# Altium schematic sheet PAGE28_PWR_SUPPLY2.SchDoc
size 431 x 304 mm; SheetNumber: 28; SheetTotal: 28
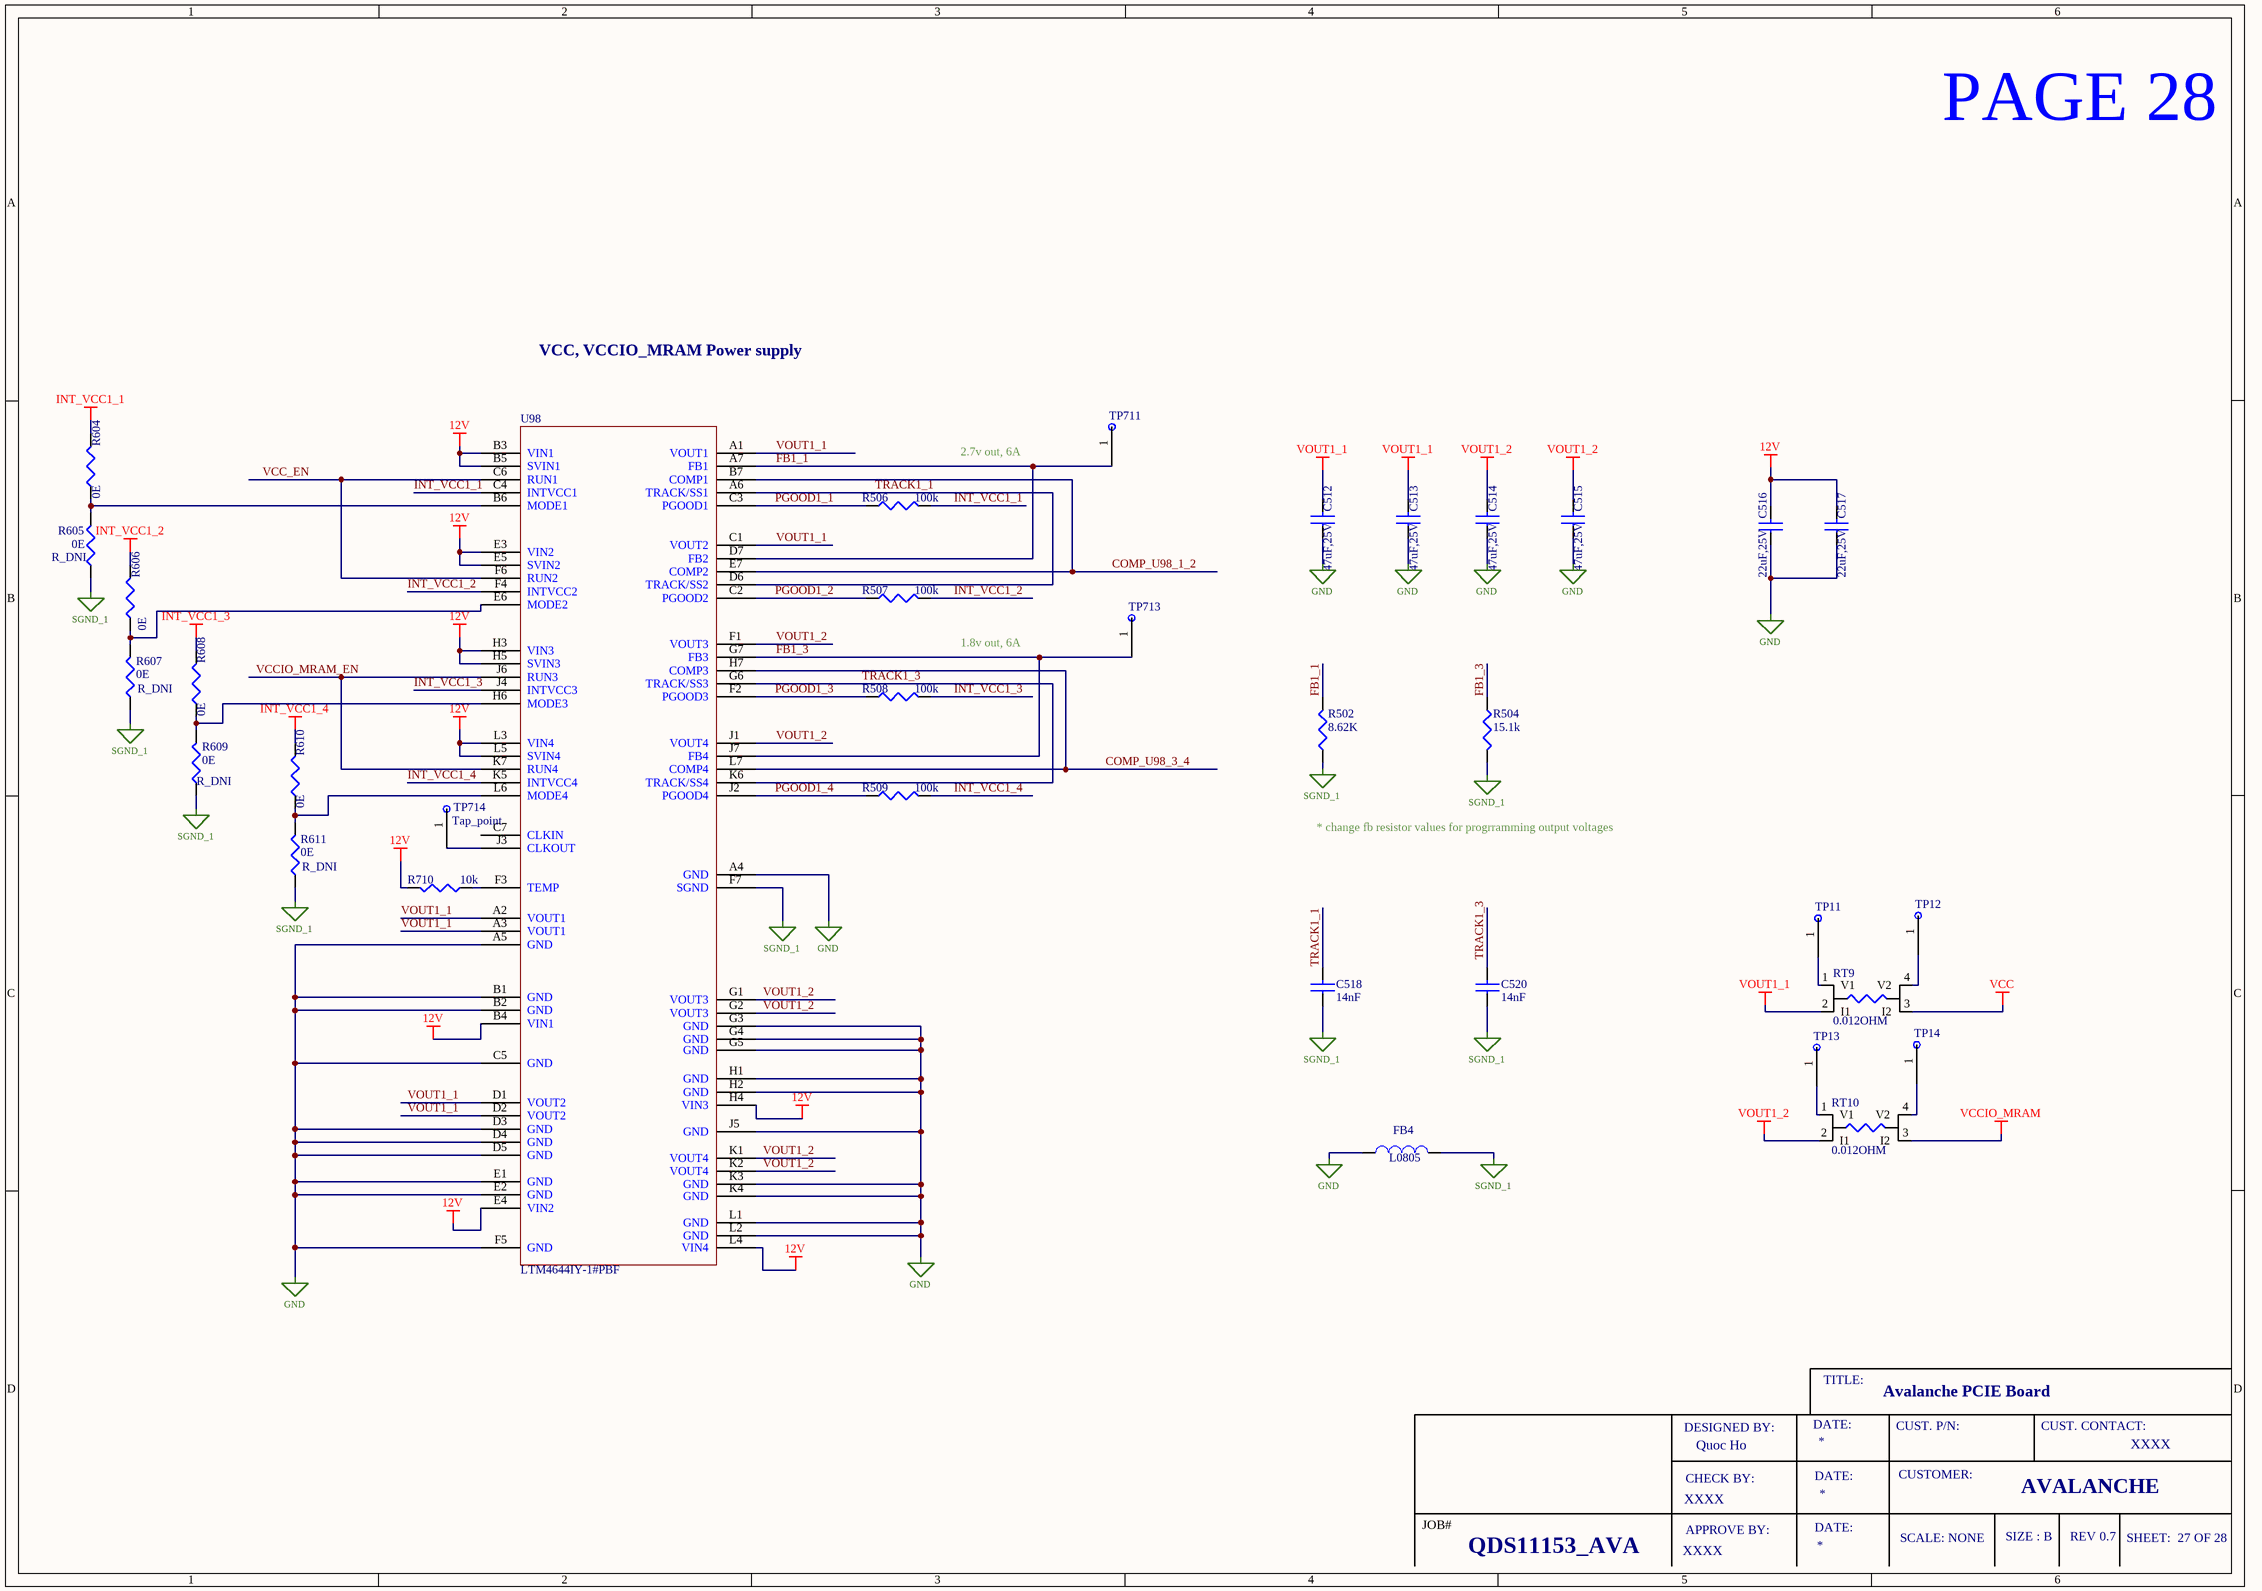
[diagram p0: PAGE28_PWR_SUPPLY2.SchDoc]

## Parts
C512  47uF,25V  [CN_1210]
C513  47uF,25V  [CN_1210]
C514  47uF,25V  [CN_1210]
C515  47uF,25V  [CN_1210]
C516  22uF,25V  [CN_1210]
C517  22uF,25V  [CN_1210]
C518  14nF  [CN_0402]
C520  14nF  [CN_0402]
FB4  L0805  [L0805]
R502  8.62K  [RN_0402]
R504  15.1k  [RN_0402]
R506  100k  [RN_0402]
R507  100k  [RN_0402]
R508  100k  [RN_0402]
R509  100k  [RN_0402]
R604  0E  [RN_0402]
R605  0E  [RN_0402]
R606  0E  [RN_0402]
R607  0E  [RN_0402]
R608  0E  [RN_0402]
R609  0E  [RN_0402]
R610  0E  [RN_0402]
R611  0E  [RN_0402]
R710  10k  [RN_0402]
RT9  0.012OHM  [LVK12]
RT10  0.012OHM  [LVK12]
TP11  Tap_point  [MINI_TESTPOINT_SMD]  (value not drawn)
TP12  Tap_point  [MINI_TESTPOINT_SMD]  (value not drawn)
TP13  Tap_point  [MINI_TESTPOINT_SMD]  (value not drawn)
TP14  Tap_point  [MINI_TESTPOINT]  (value not drawn)
TP711  Tap_point  [MINI_TESTPOINT_SMD]  (value not drawn)
TP713  Tap_point  [MINI_TESTPOINT]  (value not drawn)
TP714  Tap_point  [MINI_TESTPOINT]
U98  LTM4644IY-1#PBF  [BGA77_15X9X1P5_ANALOG]

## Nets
12V: C516.2 C517.2 R710.2 U98.B3(VIN1) U98.B4(VIN1) U98.B5(SVIN1) U98.E3(VIN2) U98.E4(VIN2) U98.E5(SVIN2) U98.H3(VIN3) U98.H4(VIN3) U98.H5(SVIN3) U98.L3(VIN4) U98.L4(VIN4) U98.L5(SVIN4)
GND: C512.1 C513.1 C514.1 C515.1 C516.1 C517.1 FB4.1 U98.A4(GND) U98.A5(GND) U98.B1(GND) U98.B2(GND) U98.C5(GND) U98.D3(GND) U98.D4(GND) U98.D5(GND) U98.E1(GND) U98.E2(GND) U98.F5(GND) U98.G3(GND) U98.G4(GND) U98.G5(GND) U98.H1(GND) U98.H2(GND) U98.J5(GND) U98.K3(GND) U98.K4(GND) U98.L1(GND) U98.L2(GND)
INT_VCC1_1: R506.2 R604.2 U98.C4(INTVCC1)
INT_VCC1_2: R507.2 R606.2 U98.F4(INTVCC2)
INT_VCC1_3: R508.2 R608.2 U98.J4(INTVCC3)
INT_VCC1_4: R509.2 R610.2 U98.K5(INTVCC4)
SGND_1: C518.1 C520.1 FB4.2 R502.1 R504.2 R605.1 R607.1 R609.1 R611.1 U98.F7(SGND)
VCC: RT9.3(I2)
VCCIO_MRAM: RT10.3(I2)
VOUT1_1: C512.2 C513.2 RT9.2(I1) U98.A1(VOUT1) U98.A2(VOUT1) U98.A3(VOUT1) U98.C1(VOUT2) U98.D1(VOUT2) U98.D2(VOUT2)
VOUT1_2: C514.2 C515.2 RT10.2(I1) U98.F1(VOUT3) U98.G1(VOUT3) U98.G2(VOUT3) U98.J1(VOUT4) U98.K1(VOUT4) U98.K2(VOUT4)
COMP_U98_1_2: U98.B7(COMP1) U98.E7(COMP2)
COMP_U98_3_4: U98.H7(COMP3) U98.L7(COMP4)
FB1_1: R502.2 TP711.1 U98.A7(FB1) U98.D7(FB2)
FB1_3: R504.1 TP713.1 U98.G7(FB3) U98.J7(FB4)
PGOOD1_1: R506.1 U98.C3(PGOOD1)
PGOOD1_2: R507.1 U98.C2(PGOOD2)
PGOOD1_3: R508.1 U98.F2(PGOOD3)
PGOOD1_4: R509.1 U98.J2(PGOOD4)
TRACK1_1: C518.2 U98.A6(TRACK/SS1) U98.D6(TRACK/SS2)
TRACK1_3: C520.2 U98.G6(TRACK/SS3) U98.K6(TRACK/SS4)
VCC_EN: U98.C6(RUN1) U98.F6(RUN2)
VCCIO_MRAM_EN: U98.J6(RUN3) U98.K7(RUN4)
NetR604_1: R604.1 R605.2 U98.B6(MODE1)
NetR606_1: R606.1 R607.2 U98.E6(MODE2)
NetR608_1: R608.1 R609.2 U98.H6(MODE3)
NetR610_1: R610.1 R611.2 U98.L6(MODE4)
NetR710_1: R710.1 U98.F3(TEMP)
NetRT9_1: RT9.1(V1) TP11.1
NetRT9_4: RT9.4(V2) TP12.1
NetRT10_1: RT10.1(V1) TP13.1
NetRT10_4: RT10.4(V2) TP14.1
NetTP714_1: TP714.1 U98.J3(CLKOUT)

Not connected (* = marked no-connect by the designer): U98 C7(CLKIN)

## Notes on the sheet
- PAGE 28
- VCC, VCCIO_MRAM Power supply
- 2.7v out, 6A
- 1.8v out, 6A
- * change fb resistor values for progrramming output voltages
- TITLE:
- Avalanche PCIE Board
- DESIGNED BY:
- CHECK BY:
- Quoc Ho
- DATE:
- CUST. P/N:
- CUSTOMER:
- CUST. CONTACT:
- XXXX
- JOB#
- APPROVE BY:
- SCALE: NONE
- SIZE : B
- AVALANCHE
- REV 0.7
- SHEET:  27 OF 28
- QDS11153_AVA

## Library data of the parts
C512-C515 = CAP: CAP CER 47UF 25V X5R 1210; Manufacturer: KYOCERA AVX; Manufacturer Part Number: KGM32LR51E476MU
C516 C517 = CAP: CAP CER 22UF 25V X5R 1210; Manufacturer Part Number: CL32A226KAJNNNE; Manufacturer: Samsung Electro-Mechanics
C518 C520 = CAP: CAP CER 0402 15NF 50V X7R 5%; Manufacturer Part Number: C0402C153J5RECTU; Manufacturer: KEMET
FB4 = INDUCTOR: FERRITE BEAD 110 OHM 0805 1LN; Manufacturer Part Number: BLM21SP111SZ1D; Manufacturer: Murata Electronics
R502 = RES: RES 8.66K OHM 1% 1/16W 0402; Manufacturer Part Number: RC0402FR-078K66L; Manufacturer: YAGEO
R504 = RES: RES SMD 15K OHM 0.1% 1/16W 0402; Manufacturer Part Number: RT0402BRD0715KL; Manufacturer: YAGEO
R506-R509 = RES: RES 100K OHM 1% 1/16W 0402; Manufacturer Part Number: RC0402FR-07100KL; Manufacturer: YAGEO
R604 R606 R608 R610 = RES: RES 0 OHM JUMPER 1/16W 0402; Manufacturer Part Number: RC0402JR-070RL; Manufacturer: YAGEO
R605 R607 R609 R611 = RES: RES 0 OHM JUMPER 1/16W 0402; Manufacturer Part Number: RC0402FR-070RL_DNI; Manufacturer: YAGEO
R710 = RES: RES 10K OHM 1% 1/16W 0402; Manufacturer Part Number: RC0402FR-0710KL; Manufacturer: YAGEO
RT9 RT10 = LVK24: RES 0.012OHM 1% 1/2W 1206; Manufacturer: OHMITE
TP11-TP14 TP711 TP713 TP714 = Tap_point: Tap_point 15X25
U98 = LTM4644IY-1#PBF_2908: DC DC CONVERTER 4X0.6-5.5V; Manufacturer: Analog Devices Inc.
